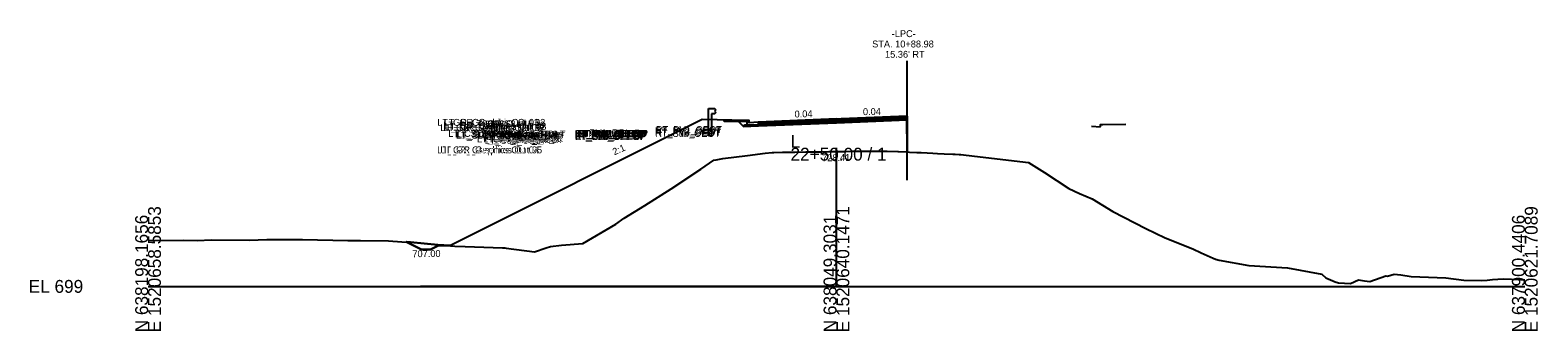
# Model space of a CAD drawing. Extents: x -26 to 3903, y -10 to 9531.
# Drawn here: x 974.3 to 1302.8, y 2490.3 to 2555.9 of the extents above; entities that cross this region are included whole.
import ezdxf

# ---------------------------------------------------------------- set-up
doc = ezdxf.new("R2010")
doc.units = 0
for name, color, linetype in [('Default', 7, 'Continuous'), ('Exist Cross Section Cell', 7, 'Continuous'), ('Exist XS Center Line Elevation Label', 7, 'Continuous'), ('Exist XS Ground Line', 7, 'Continuous'), ('Old_Level_63', 7, 'Continuous'), ('Prop CMT Conc Surface', 7, 'Continuous'), ('Prop CMT Guardrail Graphics', 7, 'Continuous'), ('Prop CMT Pvmt Course 1', 7, 'Continuous'), ('Prop CMT Pvmt Course 1 CG', 7, 'Continuous'), ('Prop CMT Pvmt Course 2', 7, 'Continuous'), ('Prop CMT Pvmt Course 3', 7, 'Continuous'), ('Prop CMT Pvmt Surface', 7, 'Continuous'), ('Prop CMT Slope Grass', 7, 'Continuous'), ('Prop CMT Subgrade Earthwork', 7, 'Continuous'), ('Prop XS DDE', 7, 'Continuous'), ('Prop XS DDE Earthwork Shape', 7, 'Continuous'), ('Prop XS DDE Elevations', 7, 'Continuous'), ('Prop XS Finish Grade Concrete', 7, 'Continuous'), ('Prop XS SE Text', 7, 'Continuous'), ('Prop XS Side Slope Text', 7, 'Continuous')]:
    doc.layers.add(name, color=color, linetype=linetype)

msp = doc.modelspace()

# ---------------------------------------------------------------- linework, layer by layer
at = {"layer": 'Exist Cross Section Cell'}
for p, q in [((1150, 2500), (1150, 2530.22)), ((1000, 2500), (1150, 2500)), ((1150, 2500), (1300, 2500))]:
    msp.add_line(p, q, dxfattribs=at)
at = {"layer": 'Exist XS Ground Line'}
msp.add_lwpolyline([(1000, 2510.04), (1007.69, 2510.07), (1010.73, 2510.02), (1013.79, 2510.12), (1022.08, 2510.1), (1025.9, 2510.19), (1032.08, 2510.24), (1033.62, 2510.23), (1043.54, 2510.03), (1044.19, 2510.02), (1046.32, 2509.97), (1052.42, 2509.9), (1055.27, 2509.74), (1057.18, 2509.63), (1063.12, 2509.07), (1066.86, 2508.8), (1069.11, 2508.7), (1077.25, 2508.42), (1077.71, 2508.41), (1078.06, 2508.35), (1084.21, 2507.54), (1086.78, 2508.38), (1087.67, 2508.73), (1090.1, 2508.97), (1094.72, 2509.36), (1101.94, 2513.59), (1103.75, 2514.84), (1108.25, 2517.63), (1113.97, 2521.24), (1120.42, 2525.55), (1123.29, 2527.53), (1123.82, 2527.62), (1125.25, 2527.91), (1130.63, 2528.56), (1134.47, 2529.02), (1135.96, 2529.19), (1136.39, 2529.21), (1138.26, 2529.26), (1138.41, 2529.26), (1139.71, 2529.28), (1140.77, 2529.29), (1140.92, 2529.29), (1143.3, 2529.32), (1143.79, 2529.32), (1145.81, 2529.31), (1146.66, 2529.33), (1148.32, 2529.37), (1149.74, 2529.41), (1150.25, 2529.42), (1150.53, 2529.43), (1150.85, 2529.43), (1151.87, 2529.44), (1153.37, 2529.46), (1155.29, 2529.45), (1155.88, 2529.45), (1158.14, 2529.45), (1158.36, 2529.45), (1160, 2529.45), (1160.81, 2529.45), (1160.91, 2529.45), (1161.04, 2529.45), (1163.39, 2529.37), (1163.55, 2529.37), (1165.17, 2529.3), (1165.94, 2529.26), (1167.52, 2529.21), (1168.46, 2529.17), (1169.76, 2529.1), (1170.98, 2529.03), (1172.01, 2528.97), (1173.51, 2528.89), (1175.36, 2528.83), (1175.9, 2528.8), (1176.77, 2528.77), (1177.02, 2528.76), (1177.09, 2528.76), (1180.1, 2528.4), (1191.88, 2527), (1195.32, 2524.81), (1200.67, 2521.31), (1202.94, 2520.23), (1205.69, 2519.07), (1210.24, 2516.34), (1217.4, 2512.59), (1221.63, 2510.6), (1227.65, 2508.21), (1229.48, 2507.31), (1232.08, 2506.12), (1232.63, 2505.91), (1233.39, 2505.69), (1239.87, 2504.52), (1248.27, 2504.01), (1255.79, 2502.7), (1256.65, 2501.83), (1258.64, 2501.01), (1259.37, 2500.78), (1262.04, 2500.66), (1263.74, 2501.42), (1265.07, 2501.19), (1266.25, 2501.05), (1269.71, 2502.32), (1270.07, 2502.26), (1271.56, 2502.65), (1272.98, 2502.53), (1275.24, 2502.14), (1282.82, 2501.85), (1286.73, 2501.34), (1290.66, 2501.29), (1291.83, 2501.39), (1292.97, 2501.52), (1295.29, 2501.66), (1297.07, 2501.54), (1300, 2501.46)], dxfattribs=at)
at = {"layer": 'Old_Level_63'}
for p, q in [((1165.41, 2529.3), (1165.37, 2537.13)), ((1131, 2535.67), (1131, 2536.17)), ((1133, 2535.83), (1131, 2535.67))]:
    msp.add_line(p, q, dxfattribs=at)
for points in [[(1125.51, 2535.95), (1125.51, 2536.27)], [(1130.51, 2535.85), (1125.51, 2535.95)], [(1130.51, 2535.85), (1125.51, 2535.95)], [(1130.5, 2536.17), (1130.5, 2535.15), (1133, 2535.25)], [(1130.51, 2536.18), (1130.51, 2535.85)], [(1133, 2535.25), (1133, 2535.83)]]:
    msp.add_lwpolyline(points, dxfattribs=at)
at = {"layer": 'Prop CMT Conc Surface'}
for points in [[(1080.46, 2533.17), (1075.46, 2533.27)], [(1080.96, 2532.66), (1080.95, 2533.16), (1080.45, 2533.16)], [(1130.46, 2536.17), (1125.46, 2536.27)], [(1130.96, 2535.66), (1130.95, 2536.16), (1130.45, 2536.16)], [(1132.96, 2535.82), (1130.96, 2535.66)], [(1205.56, 2534.95), (1207.56, 2534.79)], [(1207.56, 2534.79), (1207.56, 2535.29), (1208.06, 2535.29)], [(1208.06, 2535.29), (1213.06, 2535.39)], [(1082.96, 2532.82), (1080.96, 2532.66)]]:
    msp.add_lwpolyline(points, dxfattribs=at)
at = {"layer": 'Prop CMT Guardrail Graphics'}
for points in [[(1122.12, 2532.81), (1122.12, 2538.81)], [(1122.12, 2538.81), (1123.45, 2538.81), (1123.72, 2538.52)], [(1123.72, 2537.93), (1123.45, 2537.64), (1122.79, 2537.64)], [(1122.79, 2537.64), (1122.79, 2532.81)], [(1123.72, 2538.52), (1123.45, 2538.23)], [(1123.45, 2538.23), (1123.72, 2537.93)], [(1122.79, 2532.81), (1122.12, 2532.81)]]:
    msp.add_lwpolyline(points, dxfattribs=at)
at = {"layer": 'Prop CMT Pvmt Course 1'}
for q in [(1133, 2535.83), (1162, 2536.99)]:
    msp.add_line((1150, 2536.51), q, dxfattribs=at)
for points in [[(1162, 2536.74), (1150, 2536.26)], [(1150, 2536.26), (1150, 2536.51)], [(1150, 2536.26), (1150, 2536.51)], [(1165.41, 2537.13), (1162, 2536.99)], [(1162, 2536.99), (1162, 2536.74)], [(1162, 2536.99), (1162, 2536.74)], [(1162, 2536.74), (1165.37, 2536.88)], [(1165.37, 2536.88), (1165.37, 2537.13)], [(1165.37, 2536.88), (1165.37, 2537.13)], [(1133, 2535.58), (1150, 2536.26)], [(1133, 2535.83), (1133, 2535.58)]]:
    msp.add_lwpolyline(points, dxfattribs=at)
for points in [[(1150, 2536.26), (1150, 2536.38), (1150, 2536.38), (1150, 2536.26)], [(1150, 2536.26), (1150, 2536.38), (1150, 2536.38), (1150, 2536.26)], [(1165.37, 2536.88), (1165.37, 2537.01), (1165.37, 2537.01), (1165.37, 2536.88)], [(1165.37, 2536.88), (1165.37, 2537.01), (1165.37, 2537.01), (1165.37, 2536.88)]]:
    msp.add_lwpolyline(points, close=True, dxfattribs=at)
at = {"layer": 'Prop CMT Pvmt Course 1 CG'}
for points in [[(1133, 2535.25), (1130, 2535.13), (1129.74, 2534.87)], [(1129.74, 2534.87), (1133, 2535)], [(1133, 2535), (1133, 2535.25)]]:
    msp.add_lwpolyline(points, dxfattribs=at)
at = {"layer": 'Prop CMT Pvmt Course 2'}
for points in [[(1150, 2536.26), (1162, 2536.74)], [(1162, 2536.41), (1150, 2535.93)], [(1165.37, 2536.88), (1162, 2536.74)], [(1162, 2536.74), (1162, 2536.41)], [(1162, 2536.74), (1162, 2536.41)], [(1162, 2536.41), (1165.37, 2536.55)], [(1165.37, 2536.55), (1165.37, 2536.88)], [(1165.37, 2536.55), (1165.37, 2536.88)], [(1150, 2536.26), (1133, 2535.58)], [(1133, 2535.25), (1150, 2535.93)], [(1133, 2535.58), (1133, 2535.25)], [(1150, 2535.93), (1150, 2536.26)], [(1150, 2535.93), (1150, 2536.26)]]:
    msp.add_lwpolyline(points, dxfattribs=at)
at = {"layer": 'Prop CMT Pvmt Course 3'}
for points in [[(1150, 2535.93), (1162, 2536.41)], [(1165.37, 2536.55), (1162, 2536.41)], [(1162, 2536.41), (1162, 2536.16)], [(1162, 2536.41), (1162, 2536.16)], [(1162, 2536.16), (1165.37, 2536.3)], [(1165.37, 2536.3), (1165.37, 2536.55)], [(1165.37, 2536.3), (1165.37, 2536.55)], [(1150, 2535.93), (1133, 2535.25)], [(1133, 2535), (1150, 2535.68)], [(1133, 2535.25), (1133, 2535)], [(1162, 2536.16), (1150, 2535.68)], [(1150, 2535.68), (1150, 2535.93)], [(1150, 2535.68), (1150, 2535.93)]]:
    msp.add_lwpolyline(points, dxfattribs=at)
at = {"layer": 'Prop CMT Pvmt Surface'}
msp.add_line((1165.41, 2537.13), (1133, 2535.83), dxfattribs=at)
for points in [[(1150, 2536.51), (1133, 2535.83)], [(1150, 2536.51), (1162, 2536.99)], [(1165.41, 2537.13), (1162, 2536.99)]]:
    msp.add_lwpolyline(points, dxfattribs=at)
at = {"layer": 'Prop CMT Slope Grass'}
msp.add_line((1165.41, 2537.13), (1165.41, 2529.28), dxfattribs=at)
for points in [[(1120.72, 2536.36), (1065.75, 2508.87)], [(1130.5, 2536.17), (1120.72, 2536.36)]]:
    msp.add_lwpolyline(points, dxfattribs=at)
at = {"layer": 'Prop CMT Subgrade Earthwork'}
for points in [[(1165.41, 2536.3), (1162, 2536.16)], [(1133, 2535), (1129.74, 2534.87), (1128.4, 2536.21)], [(1150, 2535.68), (1133, 2535)], [(1150, 2535.68), (1162, 2536.16)]]:
    msp.add_lwpolyline(points, dxfattribs=at)
at = {"layer": 'Prop XS DDE'}
for p, q in [((1059.56, 2508.03), (1056.25, 2509.68)), ((1061.56, 2508.03), (1059.56, 2508.03)), ((1063.26, 2508.88), (1061.56, 2508.03)), ((1065.75, 2508.88), (1063.26, 2508.88))]:
    msp.add_line(p, q, dxfattribs=at)
at = {"layer": 'Prop XS DDE Earthwork Shape'}
for p, q in [((1056.25, 2509.68), (1059.56, 2508.03)), ((1059.56, 2508.03), (1061.56, 2508.03)), ((1061.56, 2508.03), (1063.26, 2508.88)), ((1063.26, 2508.88), (1065.73, 2508.88))]:
    msp.add_line(p, q, dxfattribs=at)
msp.add_lwpolyline([(1065.73, 2508.88), (1063.12, 2509.07), (1057.18, 2509.63), (1056.25, 2509.68)], dxfattribs=at)
at = {"layer": 'Prop XS DDE Elevations'}
msp.add_line((1150, 2500), (1059.4, 2500), dxfattribs=at)
at = {"layer": 'Prop XS Finish Grade Concrete'}
msp.add_lwpolyline([(1133, 2535.83), (1131, 2535.67), (1131, 2536.17), (1130.5, 2536.17)], dxfattribs=at)
at = {"layer": 'Prop XS SE Text'}
msp.add_line((1165.41, 2523.13), (1165.41, 2549.15), dxfattribs=at)

# ---------------------------------------------------------------- texts
at = {"layer": 'Default'}
msp.add_text('-', height=0.0001, dxfattribs=at).set_placement((1000, 2500))
at = {"layer": 'Exist Cross Section Cell'}
for s, p in [('L', (1140, 2530.22)), ('22+50.00 / 1', (1140, 2527.42)), ('EL 699', (974, 2498.6))]:
    msp.add_text(s, height=2.8, dxfattribs=at).set_placement(p)
for s, p in [('E 1520658.5853', (1002.8, 2490)), ('E 1520640.1471', (1152.8, 2490)), ('E 1520621.7089', (1302.8, 2490)), ('N 638198.1656', (1000, 2490)), ('N 638049.3031', (1150, 2490)), ('N 637900.4406', (1300, 2490))]:
    msp.add_text(s, height=2.8, rotation=90, dxfattribs=at).set_placement(p)
at = {"layer": 'Exist XS Center Line Elevation Label'}
msp.add_text('728.41', height=1.5, rotation=0.8401, dxfattribs=at).set_placement((1146.88, 2527.26))
at = {"layer": 'Prop CMT Conc Surface'}
for s, p in [('LT_GR_Graphics Out 03', (1063.02, 2535.01)), ('LT_GR_Graphics Out 02', (1064.38, 2535.01)), ('LT_GR_Graphics Out 06', (1063.67, 2533.84)), ('LT_GR_Graphics Out 07', (1064.32, 2533.84)), ('LT_GR_Graphics Out 09', (1064.34, 2534.43)), ('LT_GR_Graphics Out 08', (1064.61, 2534.13)), ('LT_CSLP_Pnt', (1065.41, 2532.6)), ('LT_SDWK_Out_Top', (1066.89, 2532.52)), ('LT_SDWK_Out_Bot', (1067.08, 2532.19)), ('LT_Sub_Trench_Out_DLT', (1067.32, 2532.45)), ('LT_GR_Out', (1070.46, 2534.72)), ('LT_SDWK_In_Top', (1072.76, 2532.42)), ('LT_CG_Top_BOC', (1072.81, 2532.41)), ('LT_SDWK_In_Bot', (1072.95, 2532.09)), ('LT_CG_Top_Face', (1073.34, 2532.41)), ('LT_CG_Top_Gut', (1073.73, 2531.91)), ('LT_PV2_OEOT', (1076.57, 2531.82)), ('LT_PV3_OEOT', (1076.57, 2531.49)), ('LT_PV1_OEOT', (1076.75, 2532.07)), ('LT_CG_Bot_IE', (1076.83, 2531.49)), ('RT_PV2_OEEOP', (1092.95, 2532.5)), ('RT_PV3_OEEOP', (1092.95, 2532.17)), ('RT_Sub_OEEOP', (1092.99, 2531.92)), ('LT_PV2_OEEOP', (1093.04, 2532.5)), ('LT_PV3_OEEOP', (1093.04, 2532.17)), ('LT_Sub_OEEOP', (1093.08, 2531.92)), ('RT_PV1_OEEOP', (1093.13, 2532.62)), ('LT_PV1_OEEOP', (1093.22, 2532.62)), ('RT_PV2_IEEOP', (1093.52, 2532.5)), ('LT_PV2_IEEOP', (1093.61, 2532.5)), ('RT_PV1_IEEOP', (1093.7, 2532.62)), ('LT_PV1_IEEOP', (1093.79, 2532.62)), ('PV2_PGL', (1095.98, 2532.5)), ('PV1_PGL', (1096.16, 2532.75)), ('RT_PV2_OEOT', (1110.48, 2533.18)), ('RT_PV3_OEOT', (1110.48, 2532.85)), ('RT_Sub_OEOT', (1110.51, 2532.6)), ('RT_PV1_OEOT', (1110.66, 2533.43)), ('LT_GR_Graphics Out 04', (1063, 2529.01)), ('LT_GR_Graphics Out 05', (1063.68, 2529.01)), ('LT_CG1_Shelf_Out', (1071.69, 2531.37)), ('LT_CG_Bot_BOC', (1073.02, 2531.39)), ('LT_Sub_OEOP', (1073.34, 2531.11)), ('LT_Sub_OEOT', (1076.61, 2531.24))]:
    msp.add_text(s, height=1.5, dxfattribs=at).set_placement(p)
at = {"layer": 'Prop XS DDE Elevations'}
msp.add_text('707.00', height=1.5, rotation=0.8401, dxfattribs=at).set_placement((1057.61, 2506.35))
at = {"layer": 'Prop XS SE Text'}
for s, rotation, p in [('STA. 10+88.98 ', 359.9946, (1157.78, 2552.09)), ('-LPC-', 359.9946, (1162.05, 2554.34)), ("15.36' RT", 359.9946, (1160.59, 2549.84)), ('0.04', 1.1458, (1140.89, 2536.81)), ('0.04', 1.1458, (1155.79, 2537.32))]:
    msp.add_text(s, height=1.5, rotation=rotation, dxfattribs=at).set_placement(p)
at = {"layer": 'Prop XS Side Slope Text'}
msp.add_text('2:1', height=1.5, rotation=23.9099, dxfattribs=at).set_placement((1101.6, 2528.56))

doc.saveas('drawing.dxf')
